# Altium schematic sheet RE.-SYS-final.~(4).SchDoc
size A3
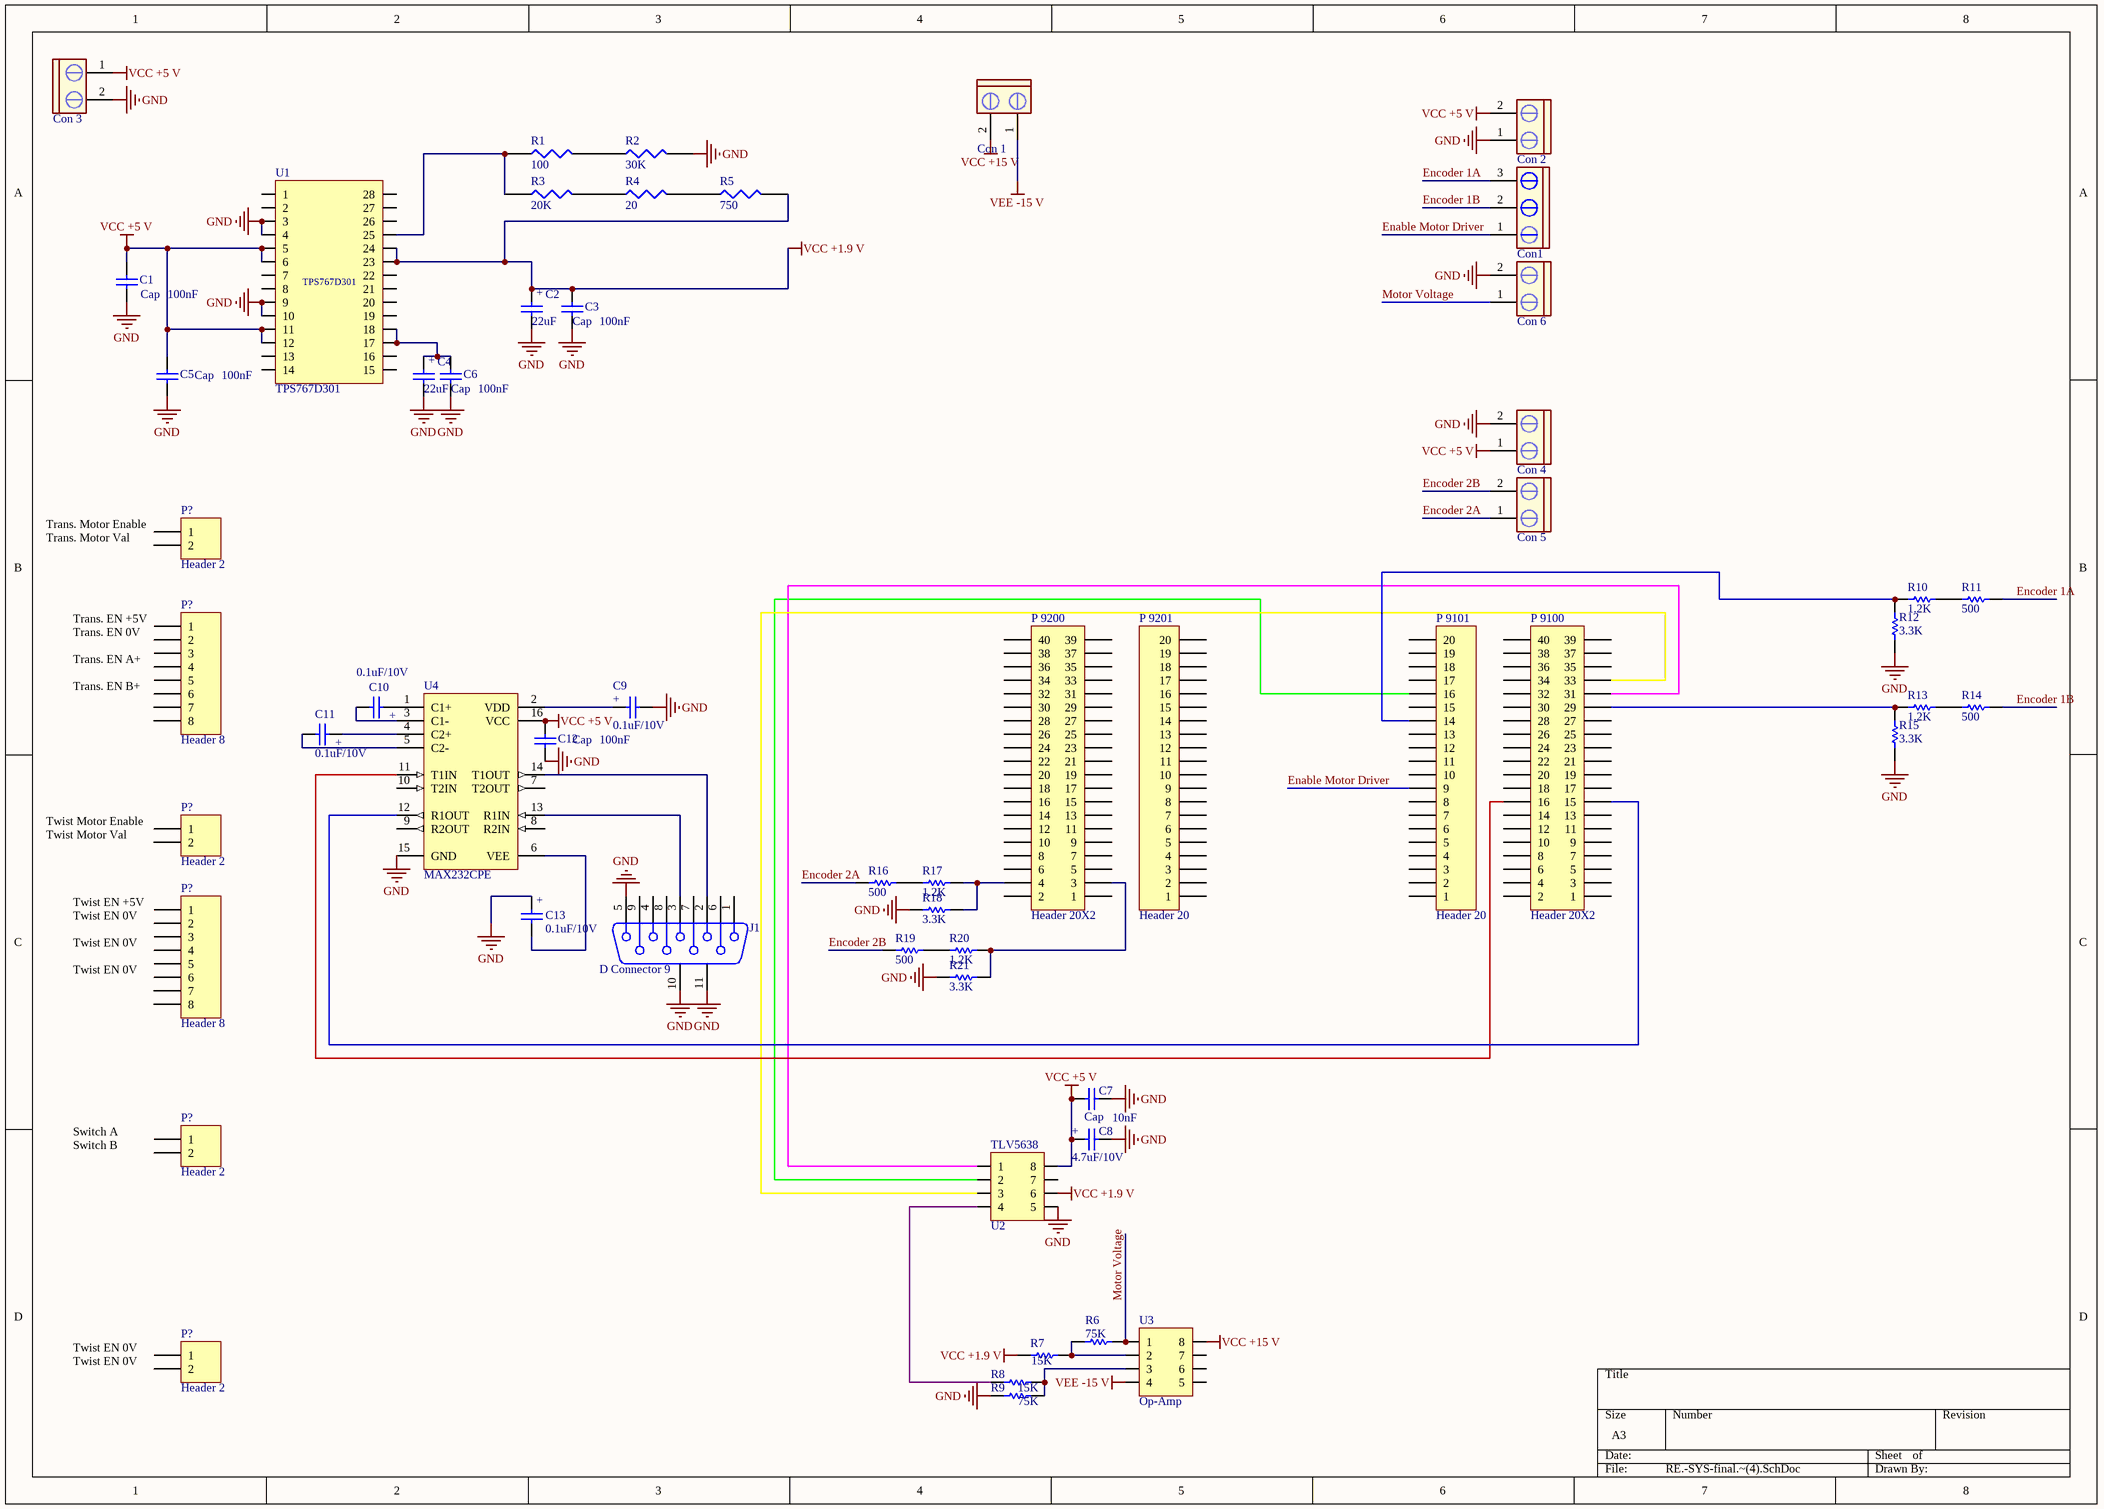
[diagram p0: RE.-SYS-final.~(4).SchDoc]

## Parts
(Parts that share a designator on the sheet are numbered #1, #2 ... from top to bottom, then left to right.)
C1  Cap  value 100nF  [RAD-0.3]
C2  value 22uF  [My_cap3300u]  (hidden comment: Cap)
C3  Cap  value 100nF  [RAD-0.3]
C4  value 22uF  [My_cap3300u]  (hidden comment: Cap)
C5  Cap  value 100nF  [RAD-0.3]
C6  Cap  value 100nF  [RAD-0.3]
C7  Cap  value 10nF  [RAD-0.3]
C8  value 4.7uF/10V  [My_cap3300u]  (hidden comment: Cap)
C9  value 0.1uF/10V  [My_cap3300u]  (hidden comment: Cap)
C10  value 0.1uF/10V  [My_cap3300u]  (hidden comment: Cap)
C11  value 0.1uF/10V  [My_cap3300u]  (hidden comment: Cap)
C12  Cap  value 100nF  [RAD-0.3]
C13  value 0.1uF/10V  [My_cap3300u]  (hidden comment: Cap)
Con1  CON3 pin Green  [My_CN3]  (value not drawn)
Con_1  CON2 pin blue  [My_CN2]  (value not drawn)
Con_2  CON2 pin blue  [My_CN2]  (value not drawn)
Con_3  CON2 pin blue  [My_CN2]  (value not drawn)
Con_4  CON2 pin blue  [My_CN2]  (value not drawn)
Con_5  CON2 pin blue  [My_CN2]  (value not drawn)
Con_6  CON2 pin blue  [My_CN2]  (value not drawn)
J1  D Connector 9  [DSUB1.385-2H9]
P?#1  Header 2  [HDR1X2]
P?#2  Header 8  [HDR1X8]
P?#3  Header 2  [HDR1X2]
P?#4  Header 8  [HDR1X8]
P?#5  Header 2  [HDR1X2]
P?#6  Header 2  [HDR1X2]
P_9100  Header 20X2  [HDR2X20]
P_9101  Header 20  [HDR1X20]
P_9200  Header 20X2  [HDR2X20]
P_9201  Header 20  [HDR1X20]
R1  value 100  [My_axial-0.4]  (hidden comment: 1k)
R2  value 30K  [My_axial-0.4]  (hidden comment: 1k)
R3  value 20K  [My_axial-0.4]  (hidden comment: 1k)
R4  value 20  [My_axial-0.4]  (hidden comment: 1k)
R5  value 750  [My_axial-0.4]  (hidden comment: 1k)
R6  value 75K  [AXIAL-0.3]  (hidden comment: Res1)
R7  value 15K  [AXIAL-0.3]  (hidden comment: Res1)
R8  value 15K  [AXIAL-0.3]  (hidden comment: Res1)
R9  value 75K  [AXIAL-0.3]  (hidden comment: Res1)
R10  value 1.2K  [AXIAL-0.3]  (hidden comment: Res1)
R11  value 500  [AXIAL-0.3]  (hidden comment: Res1)
R12  value 3.3K  [AXIAL-0.3]  (hidden comment: Res1)
R13  value 1.2K  [AXIAL-0.3]  (hidden comment: Res1)
R14  value 500  [AXIAL-0.3]  (hidden comment: Res1)
R15  value 3.3K  [AXIAL-0.3]  (hidden comment: Res1)
R16  value 500  [AXIAL-0.3]  (hidden comment: Res1)
R17  value 1.2K  [AXIAL-0.3]  (hidden comment: Res1)
R18  value 3.3K  [AXIAL-0.3]  (hidden comment: Res1)
R19  value 500  [AXIAL-0.3]  (hidden comment: Res1)
R20  value 1.2K  [AXIAL-0.3]  (hidden comment: Res1)
R21  value 3.3K  [AXIAL-0.3]  (hidden comment: Res1)
U1  TPS767D301  [SMD Reg.]
U2  TLV5638  [SMD IC FP]
U3  Op-Amp  [PCBComponent_1]
U4  MAX232CPE  [PE16A]

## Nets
GND: C1.1 C2.- C3.1 C4.- C5.1 C6.1 C7.1 C8.- C9.- C12.1 C13.+ Con_2.1 Con_3.2 Con_4.2 Con_6.2 J1.5 J1.10(MH1) J1.11(MH2) R2.2 R9.1 R12.1 R15.1 R18.2 R21.1 U1.3 U1.4 U1.9 U1.10 U2.5 U4.15(GND)
VCC +1.9 V: C2.+ C3.2 R5.2 R7.2 U1.23 U1.24 U2.6
VCC +5 V: C1.2 C5.2 C7.2 C8.+ C12.2 Con_2.2 Con_3.1 Con_4.1 U1.5 U1.6 U1.11 U1.12 U2.8 U4.16(VCC)
VCC +15 V: Con_1.2 U3.8
VEE -15 V: Con_1.1 U3.4
Enable Motor Driver: Con1.1 P_9101.9
Encoder 1A: Con1.3 R11.1
Encoder 1B: Con1.2 R14.1
Encoder 2A: Con_5.1 R16.2
Encoder 2B: Con_5.2 R19.2
Motor Voltage: Con_6.1 R6.2 U3.1
NetC4_+: C4.+ C6.2 U1.17 U1.18
NetC9_+: C9.+ U4.2(VDD)
NetC10_+: C10.+ U4.1(C1+)
NetC10_-: C10.- U4.3(C1-)
NetC11_+: C11.+ U4.4(C2+)
NetC11_-: C11.- U4.5(C2-)
NetC13_-: C13.- U4.6(VEE)
NetJ1_2: J1.2 U4.14(T1OUT)
NetJ1_3: J1.3 U4.13(R1IN)
NetP_9100_15: P_9100.15 U4.12(R1OUT)
NetP_9100_16: P_9100.16 U4.11(T1IN)
NetP_9100_29: P_9100.29 R13.2 R15.2
NetP_9100_31: P_9100.31 U2.1
NetP_9100_33: P_9100.33 U2.3
NetP_9101_14: P_9101.14 R10.2 R12.2
NetP_9101_16: P_9101.16 U2.2
NetP_9200_3: P_9200.3 R20.1 R21.2
NetP_9200_4: P_9200.4 R17.1 R18.1
NetR1_1: R1.1 R3.1 U1.25
NetR1_2: R1.2 R2.1
NetR3_2: R3.2 R4.1
NetR4_2: R4.2 R5.1
NetR6_1: R6.1 R7.1 U3.2
NetR8_1: R8.1 R9.2 U3.3
NetR8_2: R8.2 U2.4
NetR10_1: R10.1 R11.2
NetR13_1: R13.1 R14.2
NetR16_1: R16.1 R17.2
NetR19_1: R19.1 R20.2

Not connected (* = marked no-connect by the designer): J1 1 4 6 7 8 9; P?#1 1 2; P?#2 1 2 3 4 5 6 7 8; P?#3 1 2; P?#4 1 2 3 4 5 6 7 8; P?#5 1 2; P?#6 1 2; P_9100 1 2 3 4 5 6 7 8 9 10 11 12 13 14 17 18 19 20 21 22 23 24 25 26 27 28 30 32 34 35 36 37 38 39 40; P_9101 1 2 3 4 5 6 7 8 10 11 12 13 15 17 18 19 20; P_9200 1 2 5 6 7 8 9 10 11 12 13 14 15 16 17 18 19 20 21 22 23 24 25 26 27 28 29 30 31 32 33 34 35 36 37 38 39 40; P_9201 1 2 3 4 5 6 7 8 9 10 11 12 13 14 15 16 17 18 19 20; U1 1 2 7 8 13 14 15 16 19 20 21 22 26 27 28; U2 7; U3 5 6 7; U4 7(T2OUT) 8(R2IN) 9(R2OUT) 10(T2IN)

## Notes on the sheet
- (near P?#1) Trans. Motor Enable
- (near P?#1) Trans. Motor Val
- (near P?#2) Trans. EN +5V
- (near P?#2) Trans. EN 0V
- (near P?#2) Trans. EN A+
- (near P?#2) Trans. EN B+
- (near P?#3) Twist Motor Enable
- (near P?#3) Twist Motor Val
- (near P?#4) Twist EN +5V
- (near P?#4) Twist EN 0V
- (near P?#5) Switch A
- (near P?#5) Switch B
- (near P?#6) Twist EN 0V

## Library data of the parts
C1 C3 C5-C7 C12 = Cap: Capacitor
C2 C4 C8-C11 C13 = Cap Pol: CAP-3300Uf
Con1 = CON3 pin Green: Connector green screw
Con_1-Con_6 = CON2 pin blue: Connector blue screw
J1 = D Connector 9: Receptacle Assembly, 9 Position, Right Angle; PackageDocument: O; Positions: 9
P?#1 P?#3 P?#5 P?#6 = Header 2: Header, 2-Pin
P?#2 P?#4 = Header 8: Header, 8-Pin
P_9100 P_9200 = Header 20X2: Header, 20-Pin, Dual row
P_9101 P_9201 = Header 20: Header, 20-Pin
R1-R5 = Res: resistor 1/4 wat
R6-R21 = Res1: Resistor
U1 = SMD Reg.: Power Reg SMD IC
U2 = SMD IC: DAC
U3 = SMD_Comp.
U4 = MAX232CPE: +5V Powered RS-232 Driver/Receiver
